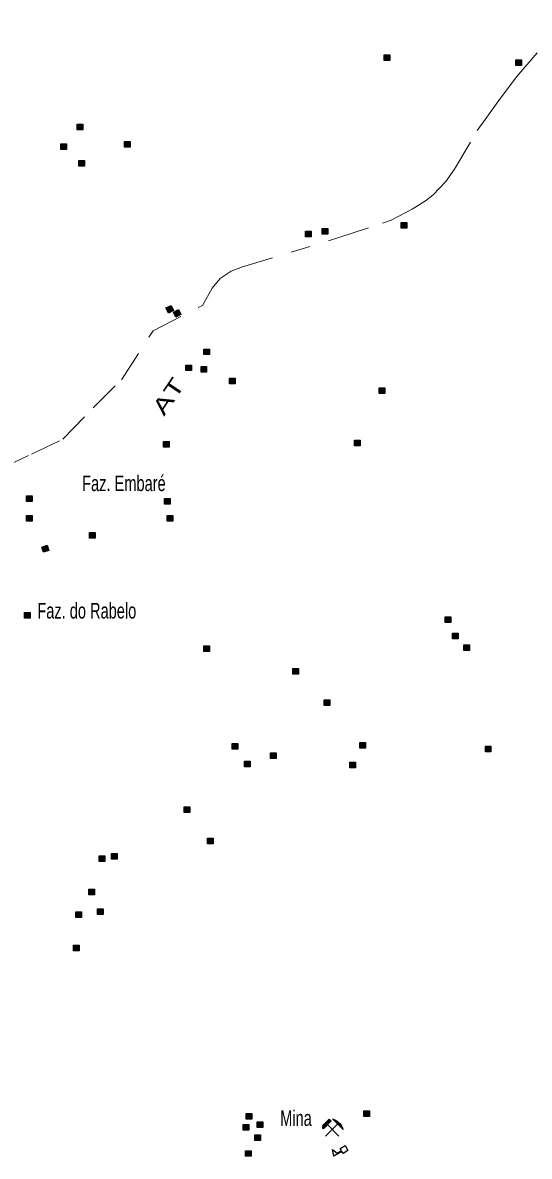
# Model space of a CAD drawing. Extents: x 220.8 to 246.7, y 7287.6 to 7315.8.
# Drawn here: x 224.49 to 227.09, y 7297.47 to 7303.29 of the extents above; entities that cross this region are included whole.
import ezdxf
from ezdxf.enums import TextEntityAlignment as Align

# ---------------------------------------------------------------- set-up
doc = ezdxf.new("R2010")
doc.units = 0
doc.header["$LTSCALE"] = 0.032
doc.linetypes.add('DOT_DASHED', pattern=[7.7, 5, -1.2, 0.3, -1.2])
for name, color, linetype, lineweight in [('2', 7, 'Continuous', 25), ('4', 7, 'Continuous', 25), ('48', 7, 'Continuous', 25), ('56', 7, 'DOT_DASHED', 13)]:
    doc.layers.add(name, color=color, linetype=linetype, lineweight=lineweight)
doc.layers.add('61', color=7, linetype='Continuous')

msp = doc.modelspace()

# ---------------------------------------------------------------- hatches: boundary and pattern name
at = {"layer": '2'}
for points in [[(226.3406, 7303.1206), (226.3696, 7303.1206), (226.3696, 7303.0916), (226.3406, 7303.0916)], [(227.0168, 7303.0944), (227.0458, 7303.0944), (227.0458, 7303.0654), (227.0168, 7303.0654)], [(224.7645, 7302.7642), (224.7935, 7302.7642), (224.7935, 7302.7352), (224.7645, 7302.7352)], [(224.6811, 7302.6636), (224.7101, 7302.6636), (224.7101, 7302.6346), (224.6811, 7302.6346)], [(225.0084, 7302.6765), (225.0374, 7302.6765), (225.0374, 7302.6475), (225.0084, 7302.6475)], [(224.7731, 7302.578), (224.8021, 7302.578), (224.8021, 7302.549), (224.7731, 7302.549)], [(226.4274, 7302.2599), (226.4564, 7302.2599), (226.4564, 7302.2309), (226.4274, 7302.2309)], [(225.9372, 7302.2153), (225.9662, 7302.2153), (225.9662, 7302.1863), (225.9372, 7302.1863)], [(226.0225, 7302.2289), (226.0515, 7302.2289), (226.0515, 7302.1999), (226.0225, 7302.1999)], [(225.2204, 7301.8216), (225.2465, 7301.834), (225.259, 7301.808), (225.2329, 7301.7954)], [(225.2584, 7301.8009), (225.2845, 7301.8133), (225.297, 7301.7873), (225.2709, 7301.7747)], [(225.4146, 7301.611), (225.4436, 7301.611), (225.4436, 7301.582), (225.4146, 7301.582)], [(225.3218, 7301.5289), (225.3508, 7301.5289), (225.3508, 7301.4999), (225.3218, 7301.4999)], [(225.4003, 7301.5217), (225.4293, 7301.5217), (225.4293, 7301.4927), (225.4003, 7301.4927)], [(225.5468, 7301.461), (225.5758, 7301.461), (225.5758, 7301.432), (225.5468, 7301.432)], [(226.3149, 7301.4112), (226.3439, 7301.4112), (226.3439, 7301.3822), (226.3149, 7301.3822)], [(225.2075, 7301.1361), (225.2365, 7301.1361), (225.2365, 7301.1071), (225.2075, 7301.1071)], [(226.1887, 7301.1427), (226.2177, 7301.1427), (226.2177, 7301.1137), (226.1887, 7301.1137)], [(224.5043, 7300.857), (224.5333, 7300.857), (224.5333, 7300.828), (224.5043, 7300.828)], [(225.2133, 7300.8436), (225.2423, 7300.8436), (225.2423, 7300.8146), (225.2133, 7300.8146)], [(224.5043, 7300.7567), (224.5333, 7300.7567), (224.5333, 7300.7277), (224.5043, 7300.7277)], [(225.2267, 7300.7567), (225.2557, 7300.7567), (225.2557, 7300.7277), (225.2267, 7300.7277)], [(224.8287, 7300.6697), (224.8577, 7300.6697), (224.8577, 7300.6407), (224.8287, 7300.6407)], [(224.583, 7300.5948), (224.6104, 7300.6044), (224.62, 7300.5771), (224.5927, 7300.5675)], [(224.4942, 7300.2584), (224.5232, 7300.2584), (224.5232, 7300.2294), (224.4942, 7300.2294)], [(226.6541, 7300.2372), (226.6831, 7300.2372), (226.6831, 7300.2082), (226.6541, 7300.2082)], [(226.6912, 7300.1529), (226.7202, 7300.1529), (226.7202, 7300.1239), (226.6912, 7300.1239)], [(225.415, 7300.0882), (225.444, 7300.0882), (225.444, 7300.0592), (225.415, 7300.0592)], [(226.7485, 7300.0922), (226.7775, 7300.0922), (226.7775, 7300.0632), (226.7485, 7300.0632)], [(225.8715, 7299.9708), (225.9005, 7299.9708), (225.9005, 7299.9418), (225.8715, 7299.9418)], [(226.0322, 7299.8103), (226.0612, 7299.8103), (226.0612, 7299.7813), (226.0322, 7299.7813)], [(225.5608, 7299.5857), (225.5898, 7299.5857), (225.5898, 7299.5567), (225.5608, 7299.5567)], [(226.216, 7299.5918), (226.245, 7299.5918), (226.245, 7299.5628), (226.216, 7299.5628)], [(226.8595, 7299.5727), (226.8885, 7299.5727), (226.8885, 7299.5437), (226.8595, 7299.5437)], [(225.7562, 7299.5392), (225.7852, 7299.5392), (225.7852, 7299.5102), (225.7562, 7299.5102)], [(225.6228, 7299.4958), (225.6518, 7299.4958), (225.6518, 7299.4668), (225.6228, 7299.4668)], [(226.1637, 7299.4912), (226.1927, 7299.4912), (226.1927, 7299.4622), (226.1637, 7299.4622)], [(225.3141, 7299.2607), (225.3431, 7299.2607), (225.3431, 7299.2317), (225.3141, 7299.2317)], [(225.4337, 7299.1001), (225.4627, 7299.1001), (225.4627, 7299.0711), (225.4337, 7299.0711)], [(224.8771, 7299.0105), (224.9061, 7299.0105), (224.9061, 7298.9815), (224.8771, 7298.9815)], [(224.9406, 7299.0217), (224.9696, 7299.0217), (224.9696, 7298.9927), (224.9406, 7298.9927)], [(224.8248, 7298.8386), (224.8538, 7298.8386), (224.8538, 7298.8096), (224.8248, 7298.8096)], [(224.7576, 7298.7228), (224.7866, 7298.7228), (224.7866, 7298.6938), (224.7576, 7298.6938)], [(224.8696, 7298.7378), (224.8986, 7298.7378), (224.8986, 7298.7088), (224.8696, 7298.7088)], [(224.7464, 7298.551), (224.7754, 7298.551), (224.7754, 7298.522), (224.7464, 7298.522)], [(226.2363, 7297.7016), (226.2653, 7297.7016), (226.2653, 7297.6726), (226.2363, 7297.6726)], [(225.6321, 7297.6882), (225.6611, 7297.6882), (225.6611, 7297.6592), (225.6321, 7297.6592)], [(225.6886, 7297.6443), (225.7176, 7297.6443), (225.7176, 7297.6153), (225.6886, 7297.6153)], [(225.6164, 7297.6317), (225.6454, 7297.6317), (225.6454, 7297.6027), (225.6164, 7297.6027)], [(225.676, 7297.5784), (225.705, 7297.5784), (225.705, 7297.5494), (225.676, 7297.5494)], [(225.6289, 7297.4967), (225.6579, 7297.4967), (225.6579, 7297.4677), (225.6289, 7297.4677)]]:
    msp.add_hatch(color=256, dxfattribs=at).paths.add_polyline_path(points)
at = {"layer": '48'}
for points in [[(226.0581, 7297.6587), (226.0678, 7297.6491), (226.0281, 7297.6095), (226.0262, 7297.6143), (226.0262, 7297.6191), (226.0272, 7297.6259), (226.0301, 7297.6307)], [(226.0746, 7297.6607), (226.0832, 7297.6568), (226.0919, 7297.652), (226.0987, 7297.6481), (226.1045, 7297.6433), (226.1123, 7297.6365), (226.119, 7297.6268), (226.1229, 7297.6201), (226.1268, 7297.6123), (226.1306, 7297.6046)]]:
    msp.add_hatch(color=256, dxfattribs=at).paths.add_polyline_path(points)

# ---------------------------------------------------------------- linework, layer by layer
at = {"layer": '2'}
for points in [[(226.3406, 7303.1206), (226.3696, 7303.1206), (226.3696, 7303.0916), (226.3406, 7303.0916)], [(227.0168, 7303.0944), (227.0458, 7303.0944), (227.0458, 7303.0654), (227.0168, 7303.0654)], [(224.7645, 7302.7642), (224.7935, 7302.7642), (224.7935, 7302.7352), (224.7645, 7302.7352)], [(224.6811, 7302.6636), (224.7101, 7302.6636), (224.7101, 7302.6346), (224.6811, 7302.6346)], [(225.0084, 7302.6765), (225.0374, 7302.6765), (225.0374, 7302.6475), (225.0084, 7302.6475)], [(224.7731, 7302.578), (224.8021, 7302.578), (224.8021, 7302.549), (224.7731, 7302.549)], [(226.4274, 7302.2599), (226.4564, 7302.2599), (226.4564, 7302.2309), (226.4274, 7302.2309)], [(225.9372, 7302.2153), (225.9662, 7302.2153), (225.9662, 7302.1863), (225.9372, 7302.1863)], [(226.0225, 7302.2289), (226.0515, 7302.2289), (226.0515, 7302.1999), (226.0225, 7302.1999)], [(225.2204, 7301.8216), (225.2465, 7301.834), (225.259, 7301.808), (225.2329, 7301.7954)], [(225.2584, 7301.8009), (225.2845, 7301.8133), (225.297, 7301.7873), (225.2709, 7301.7747)], [(225.4146, 7301.611), (225.4436, 7301.611), (225.4436, 7301.582), (225.4146, 7301.582)], [(225.3218, 7301.5289), (225.3508, 7301.5289), (225.3508, 7301.4999), (225.3218, 7301.4999)], [(225.4003, 7301.5217), (225.4293, 7301.5217), (225.4293, 7301.4927), (225.4003, 7301.4927)], [(225.5468, 7301.461), (225.5758, 7301.461), (225.5758, 7301.432), (225.5468, 7301.432)], [(226.3149, 7301.4112), (226.3439, 7301.4112), (226.3439, 7301.3822), (226.3149, 7301.3822)], [(225.2075, 7301.1361), (225.2365, 7301.1361), (225.2365, 7301.1071), (225.2075, 7301.1071)], [(226.1887, 7301.1427), (226.2177, 7301.1427), (226.2177, 7301.1137), (226.1887, 7301.1137)], [(224.5043, 7300.857), (224.5333, 7300.857), (224.5333, 7300.828), (224.5043, 7300.828)], [(225.2133, 7300.8436), (225.2423, 7300.8436), (225.2423, 7300.8146), (225.2133, 7300.8146)], [(224.5043, 7300.7567), (224.5333, 7300.7567), (224.5333, 7300.7277), (224.5043, 7300.7277)], [(225.2267, 7300.7567), (225.2557, 7300.7567), (225.2557, 7300.7277), (225.2267, 7300.7277)], [(224.8287, 7300.6697), (224.8577, 7300.6697), (224.8577, 7300.6407), (224.8287, 7300.6407)], [(224.583, 7300.5948), (224.6104, 7300.6044), (224.62, 7300.5771), (224.5927, 7300.5675)], [(224.4942, 7300.2584), (224.5232, 7300.2584), (224.5232, 7300.2294), (224.4942, 7300.2294)], [(226.6541, 7300.2372), (226.6831, 7300.2372), (226.6831, 7300.2082), (226.6541, 7300.2082)], [(226.6912, 7300.1529), (226.7202, 7300.1529), (226.7202, 7300.1239), (226.6912, 7300.1239)], [(225.415, 7300.0882), (225.444, 7300.0882), (225.444, 7300.0592), (225.415, 7300.0592)], [(226.7485, 7300.0922), (226.7775, 7300.0922), (226.7775, 7300.0632), (226.7485, 7300.0632)], [(225.8715, 7299.9708), (225.9005, 7299.9708), (225.9005, 7299.9418), (225.8715, 7299.9418)], [(226.0322, 7299.8103), (226.0612, 7299.8103), (226.0612, 7299.7813), (226.0322, 7299.7813)], [(225.5608, 7299.5857), (225.5898, 7299.5857), (225.5898, 7299.5567), (225.5608, 7299.5567)], [(226.216, 7299.5918), (226.245, 7299.5918), (226.245, 7299.5628), (226.216, 7299.5628)], [(226.8595, 7299.5727), (226.8885, 7299.5727), (226.8885, 7299.5437), (226.8595, 7299.5437)], [(225.7562, 7299.5392), (225.7852, 7299.5392), (225.7852, 7299.5102), (225.7562, 7299.5102)], [(225.6228, 7299.4958), (225.6518, 7299.4958), (225.6518, 7299.4668), (225.6228, 7299.4668)], [(226.1637, 7299.4912), (226.1927, 7299.4912), (226.1927, 7299.4622), (226.1637, 7299.4622)], [(225.3141, 7299.2607), (225.3431, 7299.2607), (225.3431, 7299.2317), (225.3141, 7299.2317)], [(225.4337, 7299.1001), (225.4627, 7299.1001), (225.4627, 7299.0711), (225.4337, 7299.0711)], [(224.8771, 7299.0105), (224.9061, 7299.0105), (224.9061, 7298.9815), (224.8771, 7298.9815)], [(224.9406, 7299.0217), (224.9696, 7299.0217), (224.9696, 7298.9927), (224.9406, 7298.9927)], [(224.8248, 7298.8386), (224.8538, 7298.8386), (224.8538, 7298.8096), (224.8248, 7298.8096)], [(224.7576, 7298.7228), (224.7866, 7298.7228), (224.7866, 7298.6938), (224.7576, 7298.6938)], [(224.8696, 7298.7378), (224.8986, 7298.7378), (224.8986, 7298.7088), (224.8696, 7298.7088)], [(224.7464, 7298.551), (224.7754, 7298.551), (224.7754, 7298.522), (224.7464, 7298.522)], [(226.2363, 7297.7016), (226.2653, 7297.7016), (226.2653, 7297.6726), (226.2363, 7297.6726)], [(225.6321, 7297.6882), (225.6611, 7297.6882), (225.6611, 7297.6592), (225.6321, 7297.6592)], [(225.6886, 7297.6443), (225.7176, 7297.6443), (225.7176, 7297.6153), (225.6886, 7297.6153)], [(225.6164, 7297.6317), (225.6454, 7297.6317), (225.6454, 7297.6027), (225.6164, 7297.6027)], [(225.676, 7297.5784), (225.705, 7297.5784), (225.705, 7297.5494), (225.676, 7297.5494)], [(225.6289, 7297.4967), (225.6579, 7297.4967), (225.6579, 7297.4677), (225.6289, 7297.4677)]]:
    msp.add_lwpolyline(points, close=True, dxfattribs=at)
at = {"layer": '4'}
for points in [[(226.1233, 7297.4932), (226.0817, 7297.4684), (226.0743, 7297.5035), (226.0984, 7297.484), (226.1208, 7297.4974)], [(226.1208, 7297.4974), (226.1146, 7297.5078), (226.1395, 7297.5226), (226.1544, 7297.4977), (226.1294, 7297.4828), (226.1233, 7297.4932)]]:
    msp.add_lwpolyline(points, dxfattribs=at)
at = {"layer": '48'}
for p, q in [((226.0397, 7297.5717), (226.1016, 7297.6336)), ((226.1084, 7297.5717), (226.0494, 7297.6307))]:
    msp.add_line(p, q, dxfattribs=at)
for points in [[(226.0581, 7297.6587), (226.0678, 7297.6491), (226.0281, 7297.6095), (226.0262, 7297.6143), (226.0262, 7297.6191), (226.0272, 7297.6259), (226.0301, 7297.6307)], [(226.0746, 7297.6607), (226.0832, 7297.6568), (226.0919, 7297.652), (226.0987, 7297.6481), (226.1045, 7297.6433), (226.1123, 7297.6365), (226.119, 7297.6268), (226.1229, 7297.6201), (226.1268, 7297.6123), (226.1306, 7297.6046)]]:
    msp.add_lwpolyline(points, close=True, dxfattribs=at)
at = {"layer": '56'}
msp.add_lwpolyline([(224.3713, 7300.9955), (224.5296, 7301.0717), (224.6908, 7301.1479), (224.8462, 7301.3092), (224.9928, 7301.4528), (225.154, 7301.7049), (225.4079, 7301.8346), (225.4575, 7301.9226), (225.499, 7301.9731), (225.5546, 7302.0105), (225.6136, 7302.0328), (226.1075, 7302.1826), (226.3318, 7302.2565), (226.3759, 7302.2716), (226.4835, 7302.328), (226.553, 7302.3713), (226.5911, 7302.4028), (226.6567, 7302.471), (226.7013, 7302.534), (226.8181, 7302.7321), (226.8585, 7302.7897), (226.9324, 7302.8919), (227.0214, 7303.0103), (227.2589, 7303.2858)], dxfattribs=at)

# ---------------------------------------------------------------- texts
at = {"layer": '61', "width": 1.45}
msp.add_text('AT', height=0.08, rotation=56.02, dxfattribs=at).set_placement((225.266, 7301.3457), align=Align.CENTER)
at = {"layer": '61', "width": 0.7}
for s, p in [('Faz. Embaré', (225.219, 7300.8817)), ('Mina', (225.9688, 7297.6236))]:
    msp.add_text(s, height=0.08, dxfattribs=at).set_placement(p, align=Align.RIGHT)
msp.add_text('Faz. do Rabelo', height=0.08, dxfattribs=at).set_placement((224.5602, 7300.2279))

doc.saveas('drawing.dxf')
